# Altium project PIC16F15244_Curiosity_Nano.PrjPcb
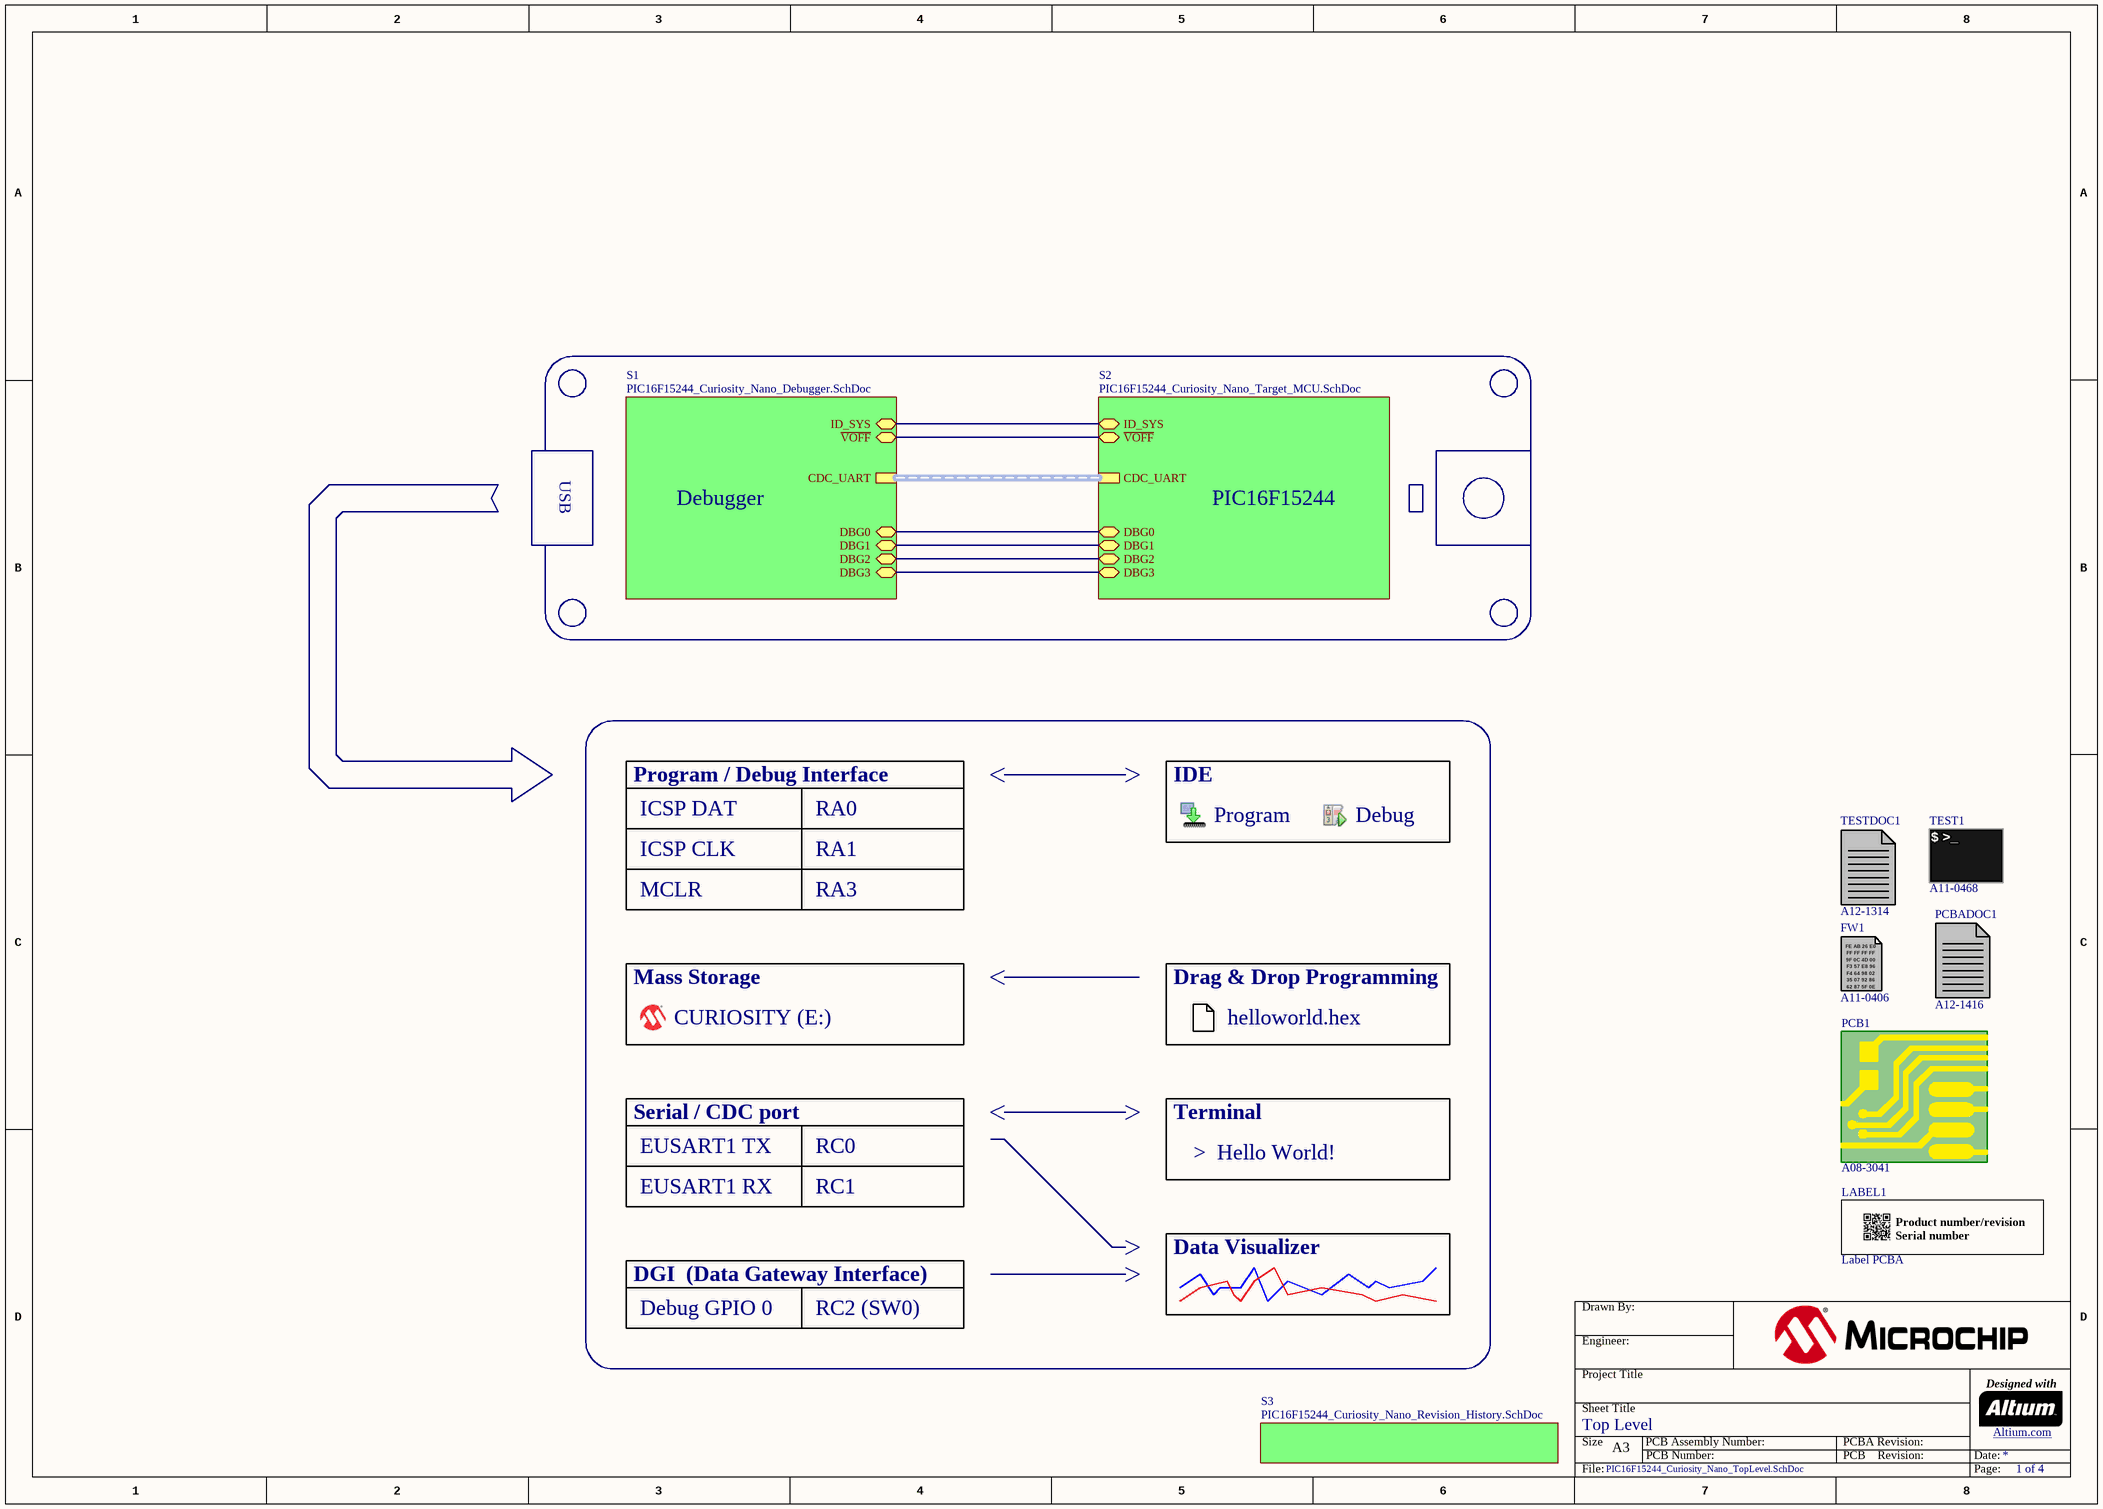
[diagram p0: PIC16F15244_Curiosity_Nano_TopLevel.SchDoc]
AN_PCB: A08-3041; AN_PCBA: A09-3317; PCB_rev: 1; PCBA_rev: 1; Project_Drawn_By: PB; Project_Engineer: PB; Target_Name: PIC16F15244
4 sheets, 64 parts. Net scope: hierarchical (ports join the sheet entries above them; power ports are global).
Board file: PIC16F15244_Curiosity_Nano.PcbDoc
Sheets:
  PIC16F15244_Curiosity_Nano_TopLevel.SchDoc
    S2 = PIC16F15244_Curiosity_Nano_Target_MCU.SchDoc
    S1 = PIC16F15244_Curiosity_Nano_Debugger.SchDoc
    S3 = PIC16F15244_Curiosity_Nano_Revision_History.SchDoc

## Sheet PIC16F15244_Curiosity_Nano_TopLevel.SchDoc: Top Level
size A3; Organization: Microchip Norway; Address1: Brøsetvegen 164; Address2: N-7069 TRONDHEIM; Address3: NORWAY; DocumentNumber: A09-3317; Revision: 1; SheetNumber: 1; SheetTotal: 4; DrawnBy: PB; Engineer: PB; PageSetup: Record=PageOptions¦CenterHorizontal=True¦CenterVertical=True¦PrintScale=1.01¦XCorrection=1.00¦YCorrection=1.00¦PrintKind=1¦BorderSize=5000000¦LeftOffset=0¦BottomOffset=0¦Orientation=2¦PaperLength=1000¦PaperWidth=1000¦Scale=100¦PaperSource=7¦PrintQuality=-4¦MediaType=1¦DitherType=10¦PaperKind=A3 (297 x 420 mm)¦PrintScaleMode=1; ProjectTitle: PIC16F15244 Curiosity Nano; PCBNumber: A08-3041; PCBRevision: 1

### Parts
FW1  AN: A11-0406  (mechanical)
LABEL1  value Label PCBA  [AP8-00317]
PCB1  AN: A08-3041  (mechanical)
PCBADOC1  AN: A12-1416  (mechanical)
TEST1  AN: A11-0468  (mechanical)
TESTDOC1  AN: A12-1314  (hidden comment: Use test fixture A13-0177)  (mechanical)

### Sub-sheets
S1 = PIC16F15244_Curiosity_Nano_Debugger.SchDoc: CDC_UART (harness UART), DBG2 (bidir), DBG1 (bidir), DBG3 (bidir), DBG0 (bidir), ~{VOFF} (bidir), ID_SYS (bidir)
S2 = PIC16F15244_Curiosity_Nano_Target_MCU.SchDoc: DBG0 (bidir), CDC_UART (harness UART), DBG1 (bidir), DBG3 (bidir), DBG2 (bidir), ~{VOFF} (bidir), ID_SYS (bidir)
S3 = PIC16F15244_Curiosity_Nano_Revision_History.SchDoc: no entries

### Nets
DBG0: sheet S2/DBG0, sheet S1/DBG0
DBG1: sheet S2/DBG1, sheet S1/DBG1
DBG2: sheet S2/DBG2, sheet S1/DBG2
DBG3: sheet S2/DBG3, sheet S1/DBG3
ID_SYS: sheet S2/ID_SYS, sheet S1/ID_SYS
~{VOFF}: sheet S2/~{VOFF}, sheet S1/~{VOFF}

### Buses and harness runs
harness sheet S1/CDC_UART = sheet S2/CDC_UART

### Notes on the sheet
- USB
- Debugger
- Program / Debug Interface
- IDE
- ICSP DAT
- ICSP CLK
- RA1
- RA0
- Program
- Debug
- MCLR
- RA3
- Mass Storage
- Drag & Drop Programming
- CURIOSITY (E:)
- helloworld.hex
- Serial / CDC port
- Terminal
- EUSART1 TX
- RC0
- >  Hello World!
- EUSART1 RX
- RC1
- Data Visualizer
- DGI  (Data Gateway Interface)
- Debug GPIO 0
- RC2 (SW0)

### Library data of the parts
FW1 = A11-0406: nEDBG firmware; PartGroup: Software,Firmware,Tools
LABEL1 = A09-0611: PCBA identification label PP Top White Gloss; Manufacturer: ACT Logimark AS; MPN: 505462; PartGroup: Mechanical devices,Packaging materials,Printed Labels,PCBA
PCB1 = A08-3041: PIC16F15244 Curiosity Nano PCB documentation; PartGroup: Mechanical devices,Printed circuit boards
PCBADOC1 = A12-1416: PIC16F15244 Curiosity Nano PCBA documentation; PartGroup: Documentation,PCBA Documents,Atmel; Value: A09-3317 PCBA files
TEST1 = A11-0468: Fixture test for PIC16F15244 Curiosity Nano; PartGroup: Software,Test software,Starter Kit; Value: PIC16F15244 Curiosity Nano test
TESTDOC1 = A12-1314: Generic Test Instructions for Curiosity Nano; PartGroup: Documentation,Procedures,Test Instructions; Value: Curiosity Nano Test Instructions

## Sheet PIC16F15244_Curiosity_Nano_Target_MCU.SchDoc: Target MCU
size A3; Organization: Microchip Norway; Address1: Brøsetvegen 164; Address2: N-7069 TRONDHEIM; Address3: NORWAY; DocumentNumber: A09-3317; Revision: 1; SheetNumber: 2; SheetTotal: 4; DrawnBy: PB; Engineer: PB; PageSetup: Record=PageOptions¦CenterHorizontal=True¦CenterVertical=True¦PrintScale=1.01¦XCorrection=1.00¦YCorrection=1.00¦PrintKind=1¦BorderSize=5000000¦LeftOffset=0¦BottomOffset=0¦Orientation=2¦PaperLength=1000¦PaperWidth=1000¦Scale=100¦PaperSource=7¦PrintQuality=-4¦MediaType=1¦DitherType=10¦PaperKind=A3 (297 x 420 mm)¦PrintScaleMode=1; ProjectTitle: PIC16F15244 Curiosity Nano; PCBNumber: A08-3041; PCBRevision: 1
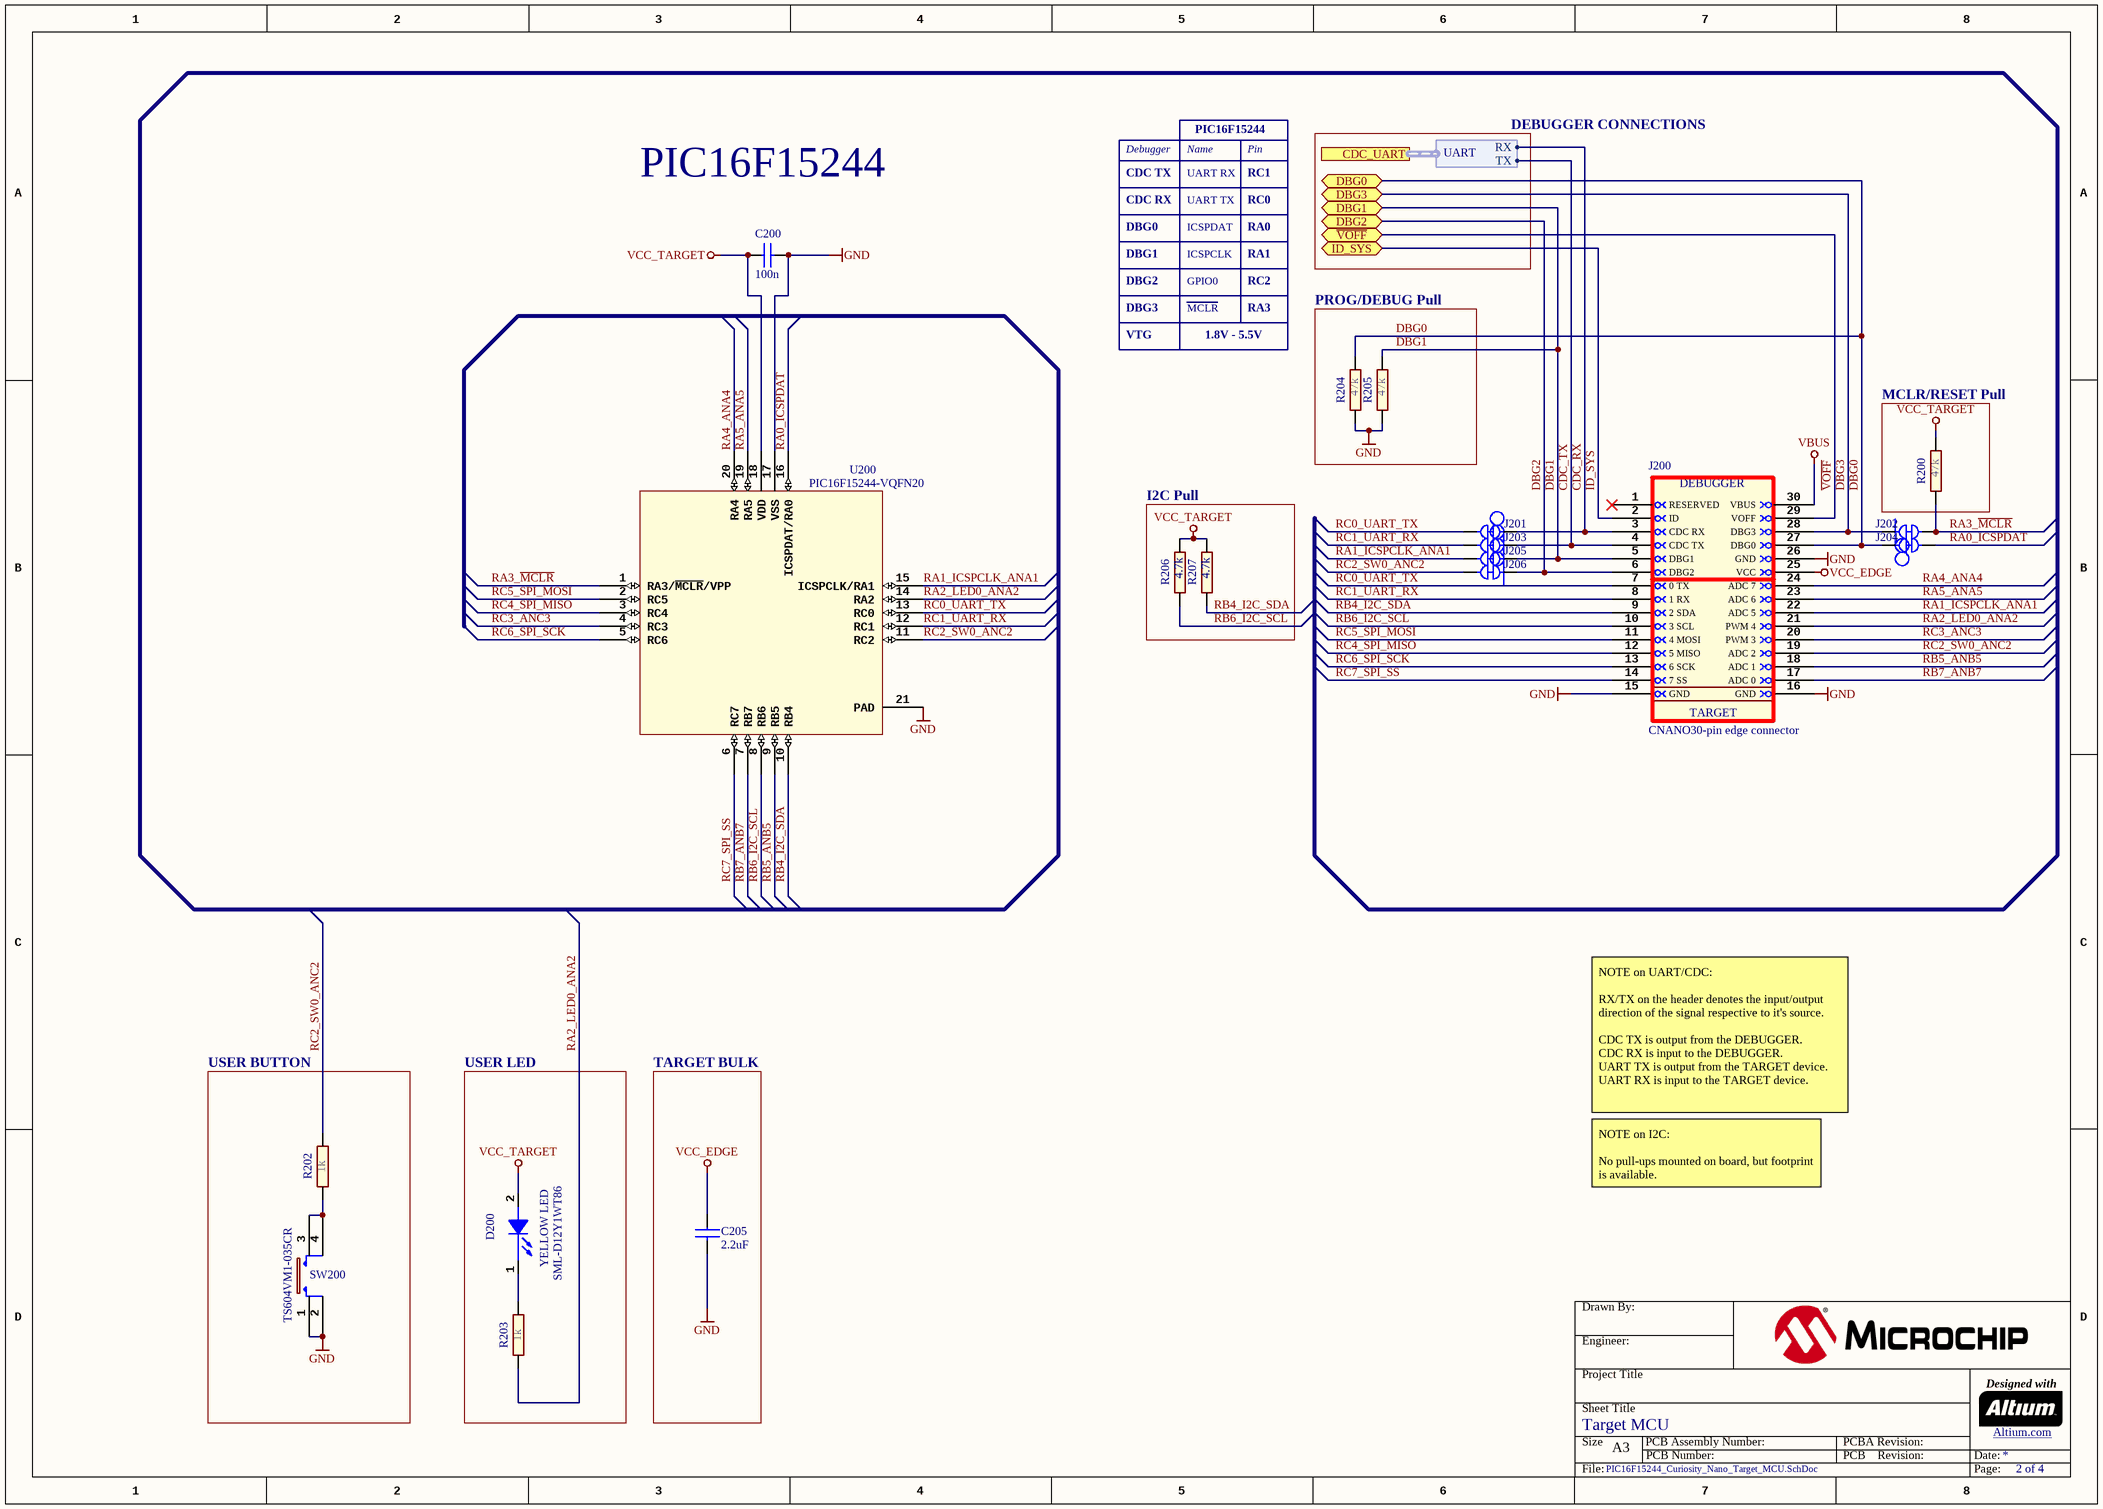
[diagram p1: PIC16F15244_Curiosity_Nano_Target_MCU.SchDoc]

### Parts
C200  value 100n  [AP1-00053]
C205  value 2.2uF  [AP1-00053]
D200  value YELLOW LED  MPN: SML-D12Y1WT86  [AP4-00169]
J200  value CNANO30-pin edge connector  [AP8-01110]  (no BOM)
J201  (no value)  [AP8-01166]  (net tie, no BOM)
J202  (no value)  [AP8-01166]  (net tie, no BOM)
J203  (no value)  [AP8-01166]  (net tie, no BOM)
J204  (no value)  [AP8-01166]  (net tie, no BOM)
J205  (no value)  [AP8-01166]  (net tie, no BOM)
J206  (no value)  [AP8-01166]  (net tie, no BOM)
R200  value 47k  [AP2-00011]
R202  value 1k  [AP2-00011]
R203  value 1k  [AP2-00011]
R204  value 47k  [AP2-00011]
R205  value 47k  [AP2-00011]
R206  value 4.7k  [AP2-00000]
R207  value 4.7k  [AP2-00000]
SW200  value TS604VM1-035CR  [AP8-00137]  (hidden comment: Rating: DC 12V 50mA / Max 0.1 ohm contact resistance)
U200  value PIC16F15244-VQFN20  [AP6-00494]

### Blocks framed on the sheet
PROG/DEBUG Pull: R204 R205
MCLR/RESET Pull: R200
I2C Pull: R206 R207
USER BUTTON: R202 SW200
USER LED: D200 R203
TARGET BULK: C205

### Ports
CDC_UART (harness UART), DBG0 (bidir), DBG1 (bidir), DBG2 (bidir), DBG3 (bidir), ID_SYS (bidir), ~{VOFF} (bidir)

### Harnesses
UART: TX, RX

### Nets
GND: C200.2 C205.2 J200.15(GND) J200.16(GND) J200.26(GND) R204.2 R205.2 SW200.1 SW200.2 U200.17(VSS) U200.21(PAD)
VBUS: J200.30(VBUS)
VCC_EDGE: C205.1 J200.25(VCC)
VCC_TARGET: C200.1 D200.2(ANODE) R200.1 R206.1 R207.1 U200.18(VDD)
CDC_RX: J200.3(CDC_RX) J201.1 ; port CDC_UART.RX
CDC_TX: J200.4(CDC_TX) J203.1 ; port CDC_UART.TX
DBG0: J200.27(DBG0) J204.1 R204.1 ; port DBG0
DBG1: J200.5(DBG1) J205.1 R205.1 ; port DBG1
DBG2: J200.6(DBG2) J206.1 ; port DBG2
DBG3: J200.28(DBG3) J202.1 ; port DBG3
ID_SYS: J200.2(ID) ; port ID_SYS
RA0_ICSPDAT: J204.2 U200.16(ICSPDAT/RA0)
RA1_ICSPCLK_ANA1: J200.22(ADC_5) J205.2 U200.15(ICSPCLK/RA1)
RA2_LED0_ANA2: J200.21(PWM_4) R203.1 U200.14(RA2)
RA3_~{MCLR}: J202.2 R200.2 U200.1(RA3/~{MCLR}/VPP)
RA4_ANA4: J200.24(ADC_7) U200.20(RA4)
RA5_ANA5: J200.23(ADC_6) U200.19(RA5)
RB4_I2C_SDA: J200.9(2_SDA) R207.2 U200.10(RB4)
RB5_ANB5: J200.18(ADC_1) U200.9(RB5)
RB6_I2C_SCL: J200.10(3_SCL) R206.2 U200.8(RB6)
RB7_ANB7: J200.17(ADC_0) U200.7(RB7)
RC0_UART_TX: J200.7(0_TX) J201.2 U200.13(RC0)
RC1_UART_RX: J200.8(1_RX) J203.2 U200.12(RC1)
RC2_SW0_ANC2: J200.19(ADC_2) J206.2 R202.1 U200.11(RC2)
RC3_ANC3: J200.20(PWM_3) U200.4(RC3)
RC4_SPI_MISO: J200.12(5_MISO) U200.3(RC4)
RC5_SPI_MOSI: J200.11(4_MOSI) U200.2(RC5)
RC6_SPI_SCK: J200.13(6_SCK) U200.5(RC6)
RC7_SPI_SS: J200.14(7_SS) U200.6(RC7)
~{VOFF}: J200.29(VOFF) ; port ~{VOFF}
NetD200_1: D200.1(CATHODE) R203.2
NetR202_2: R202.2 SW200.3 SW200.4

Not connected (* = marked no-connect by the designer): J200 1(RESERVED)*

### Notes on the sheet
- Debugger
- CDC TX
- UART RX
- Name
- RC1
- Pin
- DEBUGGER CONNECTIONS
- DBG0
- CDC RX
- ICSPDAT
- UART TX
- RA0
- RC0
- DBG1
- DBG2
- DBG3
- ICSPCLK
- GPIO0
- MCLR
- RA1
- RC2
- RA3
- VTG
- 1.8V - 5.5V
- NOTE on UART/CDC:
  RX/TX on the header denotes the input/output direction of the signal respective to it's source.
  CDC TX is output from the DEBUGGER.
  CDC RX is input to the DEBUGGER.
  UART TX is output from the TARGET device.
  UART RX is input to the TARGET device.
- NOTE on I2C:
  No pull-ups mounted on board, but footprint is available.

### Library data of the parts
C200 = A01-0246: Ceramic capacitor, SMD 0402, X7R, 16V, +/-10%; Manufacturer: Kemet; MPN: C0402C104K4RACTU; PartGroup: Capacitors,Ceramic,SMD 0402; TemperatureRange: -55 - +125 deg C
C205 = A01-0493: CAP CER 2.2UF 10V 10% X5R 0402; PartGroup: Capacitors,Ceramic,SMD 0402; Manufacturer: tdk; MPN: C1005X5R1A225K; Tolerance: +/-10%; TemperatureRange: -55 to 85C
D200 = A10-0218: LED, SMD 0603, Yellow, Wave length=590nm, 100mcd @ (20mA, 2.2Vf) rohm; PartGroup: Opto,LEDs,SMD; TemperatureRange: -40 to +85
J200 = A08-2846: Curiosity Nano 30-pin edge connector with castellations, 100-mil pitch.; PartGroup: Mechanical devices,Connectors,Pin headers
J201-J206 = A08-2981: Closed Link 0402 w/50mil hole; PartGroup: Mechanical devices,PCB implemented components
R200 R204 R205 = A02-0252: Thick film resistor, SMD 0402, 1/16W, 1%; Manufacturer: KOA; MPN: RK73H1ETTP4702F; PartGroup: Resistors,SMD,0402 1%; TemperatureRange: -55 - +125 deg C
R202 = A02-0212: Thick film resistor, SMD 0402, 1/16W, 1%; Manufacturer: ASJ Holdings; MPN: CR10-1001-FK; PartGroup: Resistors,SMD,0402 1%; TemperatureRange: -55 - +125 deg C
R203 = A02-0212: Thick film resistor, SMD 0402, 1/16W, 1%; PartGroup: Resistors,SMD,0402 1%; Manufacturer: ASJ Holdings; MPN: CR10-1001-FK; TemperatureRange: -55 - +125 deg C
R206 R207 = A02-1016: Thick film resistror, SMD 0402, 1/16W, 1%; PartGroup: Resistors,SMD,0402 1%; Manufacturer: Yageo; MPN: RC0402FR-074K7L; TemperatureRange: -55 to +155 deg C
SW200 = A08-2830: SWITCH, SMD, 260gf, 6.4mm X 6.2mm; PartGroup: Mechanical devices,Switches,SMD; Manufacturer: Dailywell Electronics Co.LTD; MPN: TS604VM1-035CR-R; TemperatureRange: -40 - +85 deg C
U200 = A06-1719: PIC 8-bit RISC MCU, VQFN-20, 3mm x 3mm; PartGroup: Integrated Circuits,MCU, MPU, DSP,PIC; Manufacturer: Microchip; MPN: PIC16F15244-I/REB; TemperatureRange: -40°C to 85°C

## Sheet PIC16F15244_Curiosity_Nano_Debugger.SchDoc: Debugger
size A3; Organization: Microchip Norway; Address1: Brøsetvegen 164; Address2: N-7069 TRONDHEIM; Address3: NORWAY; DocumentNumber: A09-3317; Revision: 1; SheetNumber: 3; SheetTotal: 4; DrawnBy: PB; Engineer: PB; PageSetup: Record=PageOptions¦CenterHorizontal=True¦CenterVertical=True¦PrintScale=1.01¦XCorrection=1.00¦YCorrection=1.00¦PrintKind=1¦BorderSize=5000000¦LeftOffset=0¦BottomOffset=0¦Orientation=2¦PaperLength=1000¦PaperWidth=1000¦Scale=100¦PaperSource=7¦PrintQuality=-4¦MediaType=1¦DitherType=10¦PaperKind=A3 (297 x 420 mm)¦PrintScaleMode=1; ProjectTitle: PIC16F15244 Curiosity Nano; PCBNumber: A08-3041; PCBRevision: 1
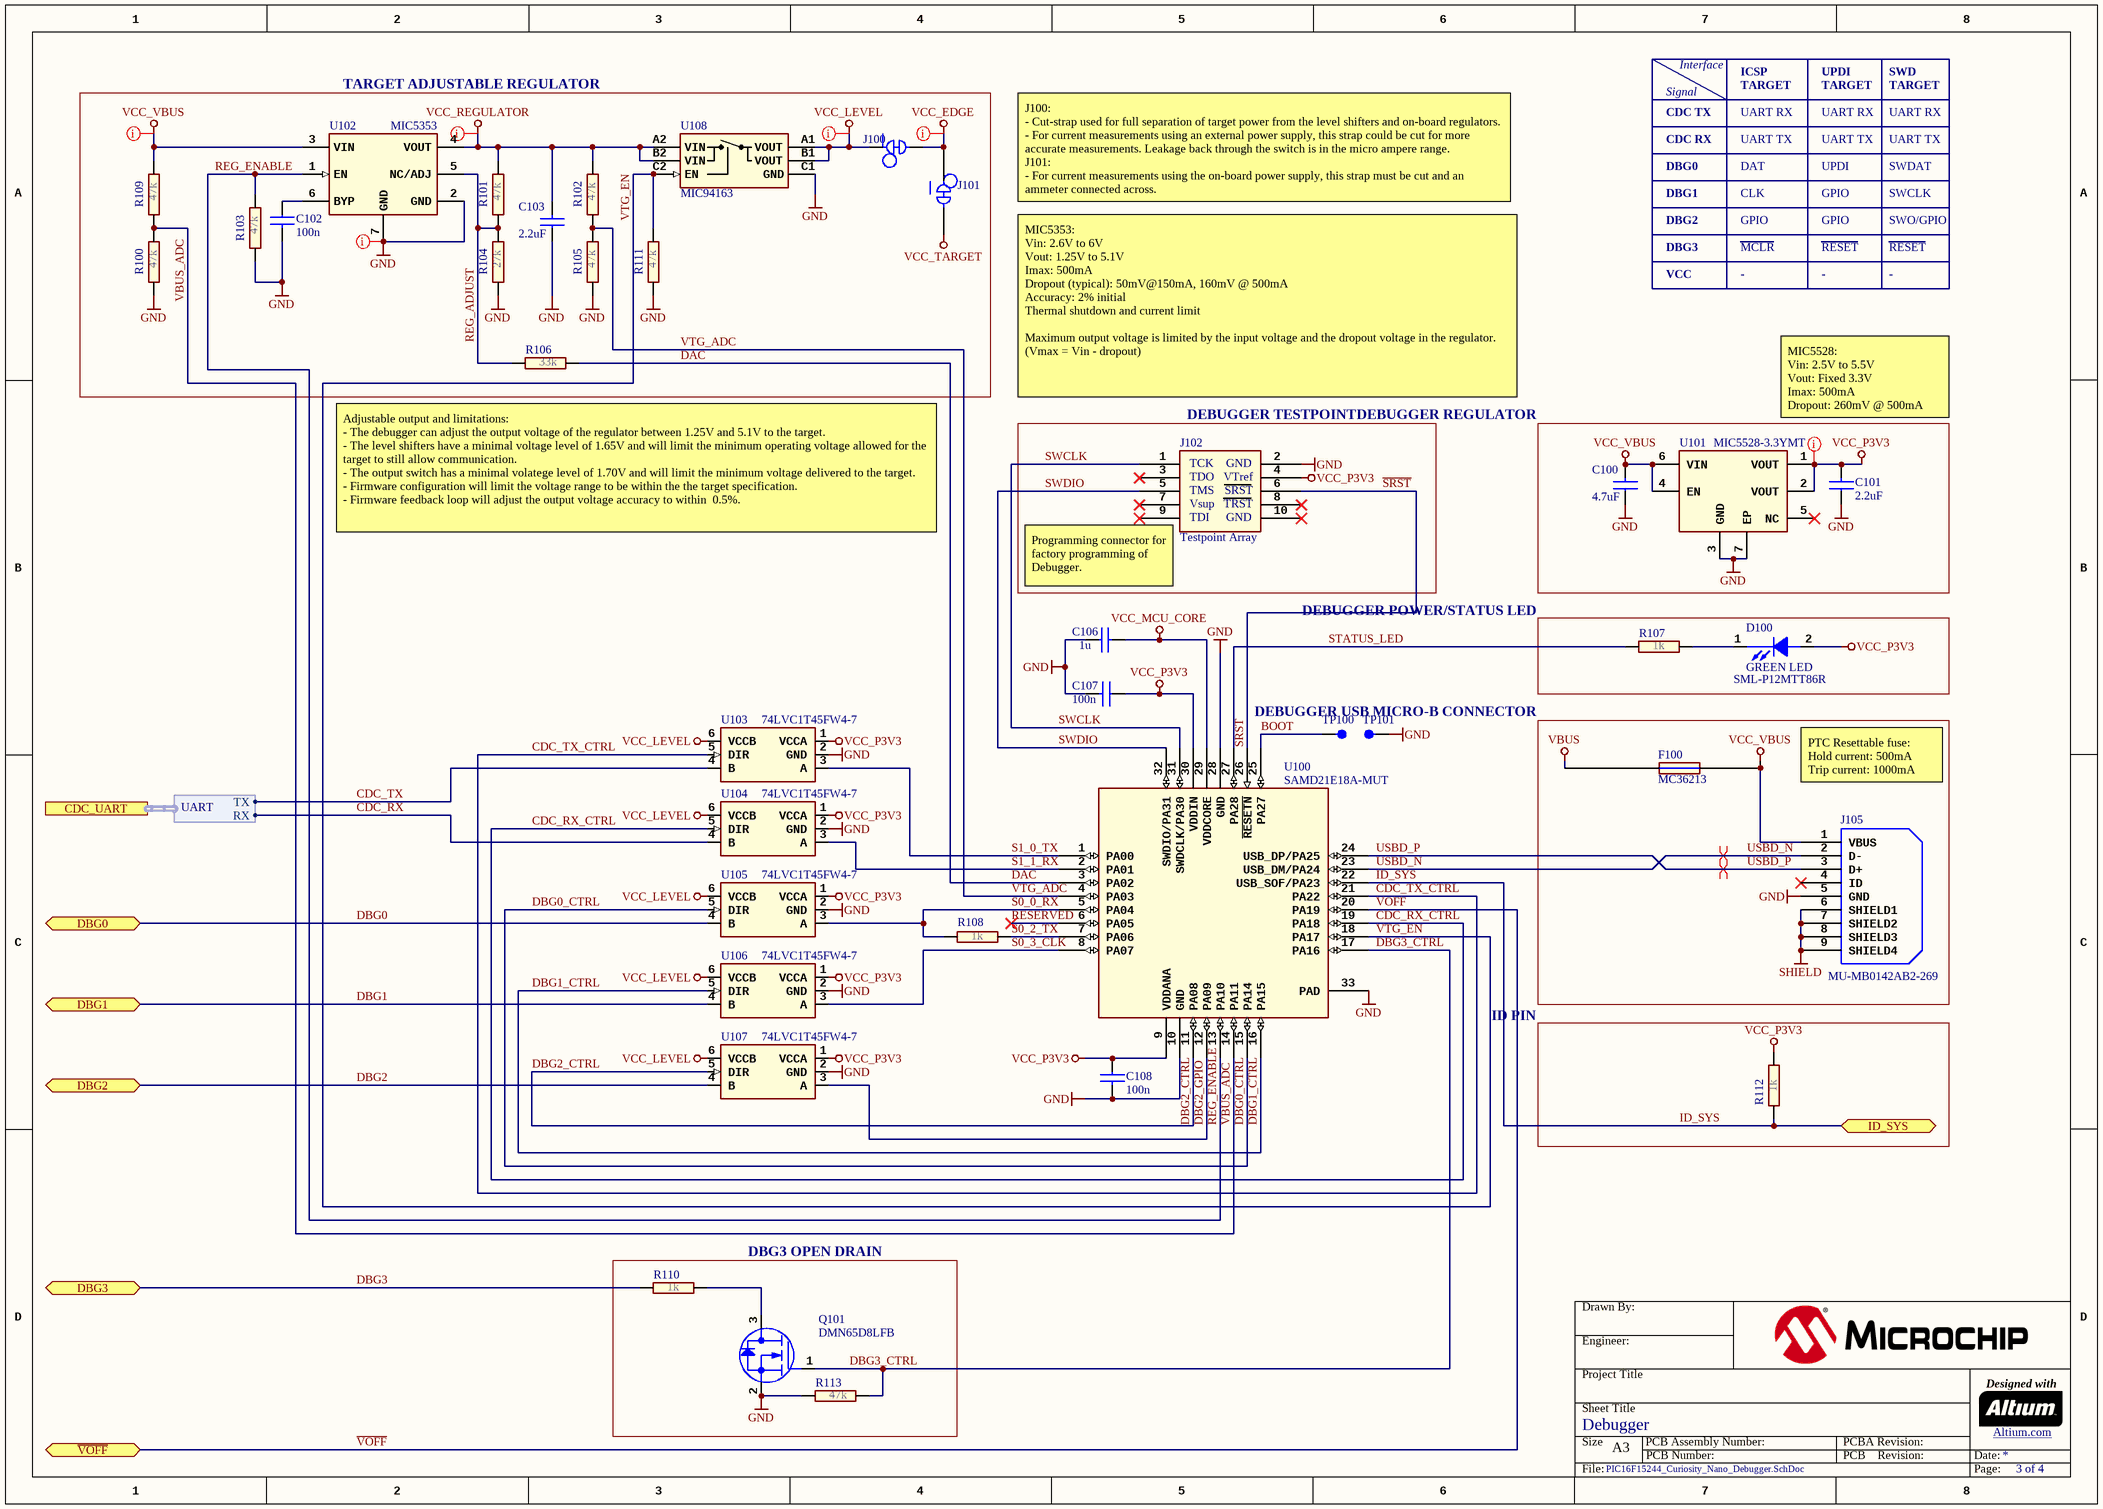
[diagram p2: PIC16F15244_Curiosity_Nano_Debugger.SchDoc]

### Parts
C100  value 4.7uF  [AP1-00039]
C101  value 2.2uF  [AP1-00053]  (hidden comment: Farnell no: 1288200)
C102  value 100n  [AP1-00053]
C103  value 2.2uF  [AP1-00053]
C106  value 1u  [AP1-00053]
C107  value 100n  [AP1-00053]
C108  value 100n  [AP1-00053]
D100  value GREEN LED  MPN: SML-P12MTT86R  [AP4-00160]  (hidden comment: Replacement to A10-0183 / Not proven to be as good at If = 1mA)
F100  value MC36213  [AP2-00002]  (hidden comment: Farnell no: 1861197)
J100  (no value)  [AP8-00595]  (net tie, no BOM)
J101  (no value)  [AP8-01183]  (net tie, no BOM)
J102  value Testpoint Array  [AP8-00997]  (no BOM)
J105  value MU-MB0142AB2-269  [AP8-01099]
Q101  value DMN65D8LFB  [AP5-00056]
R100  value 47k  [AP2-00011]
R101  value 47k  [AP2-00011]
R102  value 47k  [AP2-00011]
R103  value 47k  [AP2-00011]
R104  value 27k  [AP2-00011]
R105  value 47k  [AP2-00011]
R106  value 33k  [AP2-00011]
R107  value 1k  [AP2-00011]
R108  value 1k  [AP2-00011]
R109  value 47k  [AP2-00011]
R110  value 1k  [AP2-00011]
R111  value 47k  [AP2-00011]
R112  value 1k  [AP2-00011]
R113  value 47k  [AP2-00011]
TP100  PCB implemented component.  [AP8-00870]  (value not drawn)  (no BOM)
TP101  PCB implemented component.  [AP8-00870]  (value not drawn)  (no BOM)
U100  value SAMD21E18A-MUT  [AP6-00418]  (hidden comment: QFN32)
U101  value MIC5528-3.3YMT  [AP6-00481]
U102  value MIC5353  [AP6-00504]  (hidden comment: Marking code: AAR)
U103  value 74LVC1T45FW4-7  [AP6-00505]  (hidden comment: 1.05 x 1.05 x 0.4mm)
U104  value 74LVC1T45FW4-7  [AP6-00505]  (hidden comment: 1.05 x 1.05 x 0.4mm)
U105  value 74LVC1T45FW4-7  [AP6-00505]  (hidden comment: 1.05 x 1.05 x 0.4mm)
U106  value 74LVC1T45FW4-7  [AP6-00505]  (hidden comment: 1.05 x 1.05 x 0.4mm)
U107  value 74LVC1T45FW4-7  [AP6-00505]  (hidden comment: 1.05 x 1.05 x 0.4mm)
U108  value MIC94163  [AP6-00513]

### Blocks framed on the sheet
TARGET ADJUSTABLE REGULATOR: C102 C103 J100 J101 R100-R106 R109 R111 U102 U108
DEBUGGER TESTPOINT: J102
DEBUGGER REGULATOR: C100 C101 U101
DEBUGGER POWER/STATUS LED: D100 R107
DEBUGGER USB MICRO-B CONNECTOR: F100 J105
ID PIN: R112
DBG3 OPEN DRAIN: Q101 R110 R113

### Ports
CDC_UART (harness UART), DBG0 (bidir), DBG1 (bidir), DBG2 (bidir), DBG3 (bidir), ID_SYS (bidir), ~{VOFF} (bidir)

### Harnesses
UART: RX, TX

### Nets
GND: C100.1 C101.1 C102.2 C103.1 C106.1 C107.2 C108.2 J102.2 J105.5(GND) Q101.2(S) R100.2 R103.2 R104.1 R105.1 R111.2 R113.2 TP101.1 U100.10(GND) U100.28(GND) U100.33(PAD) U101.3(GND) U101.7(EP) U102.2(GND) U102.7(GND) U103.2(GND) U104.2(GND) U105.2(GND) U106.2(GND) U107.2(GND) U108.C1(GND)
SHIELD: J105.6(SHIELD1) J105.7(SHIELD2) J105.8(SHIELD3) J105.9(SHIELD4)
VBUS: F100.1
VCC_EDGE: J100.2 J101.1
VCC_LEVEL: J100.1 U103.6(VCCB) U104.6(VCCB) U105.6(VCCB) U106.6(VCCB) U107.6(VCCB) U108.A1(VOUT) U108.B1(VOUT)
VCC_MCU_CORE: C106.2 U100.29(VDDCORE)
VCC_P3V3: C101.2 C107.1 C108.1 D100.2(ANODE) J102.4 R112.1 U100.9(VDDANA) U100.30(VDDIN) U101.1(VOUT) U101.2(VOUT) U103.1(VCCA) U104.1(VCCA) U105.1(VCCA) U106.1(VCCA) U107.1(VCCA)
VCC_REGULATOR: C103.2 R101.1 R102.2 U102.4(VOUT) U108.A2(VIN) U108.B2(VIN)
VCC_TARGET: J101.2
VCC_VBUS: C100.2 F100.2 J105.1(VBUS) R109.2 U101.4(EN) U101.6(VIN) U102.3(VIN)
BOOT: TP100.1 U100.25(PA27)
CDC_RX: U104.4(B) ; port CDC_UART.RX
CDC_RX_CTRL: U100.19(PA18) U104.5(DIR)
CDC_TX: U103.4(B) ; port CDC_UART.TX
CDC_TX_CTRL: U100.21(PA22) U103.5(DIR)
DAC: R106.2 U100.3(PA02)
DBG0: U105.4(B) ; port DBG0
DBG0_CTRL: U100.15(PA14) U105.5(DIR)
DBG1: U106.4(B) ; port DBG1
DBG1_CTRL: U100.16(PA15) U106.5(DIR)
DBG2: U107.4(B) ; port DBG2
DBG2_CTRL: U100.11(PA08) U107.5(DIR)
DBG2_GPIO: U100.12(PA09) U107.3(A)
DBG3: R110.2 ; port DBG3
DBG3_CTRL: Q101.1(G) R113.1 U100.17(PA16)
ID_SYS: R112.2 U100.22(USB_SOF/PA23) ; port ID_SYS
REG_ADJUST: R101.2 R104.2 R106.1 U102.5(NC/ADJ)
REG_ENABLE: R103.1 U100.13(PA10) U102.1(EN)
RESERVED: U100.6(PA05)
S0_0_RX: R108.1 U100.5(PA04) U105.3(A)
S0_2_TX: R108.2 U100.7(PA06)
S0_3_CLK: U100.8(PA07) U106.3(A)
S1_0_TX: U100.1(PA00) U103.3(A)
S1_1_RX: U100.2(PA01) U104.3(A)
~{SRST}: J102.6 U100.26(~{RESETN})
STATUS_LED: R107.2 U100.27(PA28)
SWCLK: J102.1 U100.31(SWDCLK/PA30)
SWDIO: J102.5 U100.32(SWDIO/PA31)
USBD_N: J105.2(D-) U100.23(USB_DM/PA24)
USBD_P: J105.3(D+) U100.24(USB_DP/PA25)
~{VOFF}: U100.20(PA19) ; port ~{VOFF}
VBUS_ADC: R100.1 R109.1 U100.14(PA11)
VTG_ADC: R102.1 R105.2 U100.4(PA03)
VTG_EN: R111.1 U100.18(PA17) U108.C2(EN)
NetC102_1: C102.1 U102.6(BYP)
NetD100_1: D100.1(CATHODE) R107.1
NetQ101_3: Q101.3(D) R110.1

Not connected (* = marked no-connect by the designer): J102 3* 7* 8* 9* 10*; J105 4(ID)*; U101 5(NC)*

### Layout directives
net class Power: GND, VCC_EDGE, VCC_LEVEL, VCC_P3V3, VCC_REGULATOR, VCC_VBUS
differential pair: USBD_N, USBD_P

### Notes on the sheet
- Signal
- Interface
- ICSP
- TARGET
- UPDI
- SWD
- DBG0
- CDC TX
- CDC RX
- DAT
- UART RX
- UART TX
- SWDAT
- J100:
  - Cut-strap used for full separation of target power from the level shifters and on-board regulators.
  - For current measurements using an external power supply, this strap could be cut for more accurate measurements. Leakage back through the switch is in the micro ampere range.
  J101:
  - For current measurements using the on-board power supply, this strap must be cut and an ammeter connected across.
- DBG1
- DBG2
- CLK
- GPIO
- SWCLK
- SWO/GPIO
- DBG3
- VCC
- MCLR
- -
- RESET
- MIC5353:
  Vin: 2.6V to 6V
  Vout: 1.25V to 5.1V
  Imax: 500mA
  Dropout (typical): 50mV@150mA, 160mV @ 500mA
  Accuracy: 2% initial
  Thermal shutdown and current limit
  Maximum output voltage is limited by the input voltage and the dropout voltage in the regulator.
  (Vmax = Vin - dropout)
- MIC5528:
  Vin: 2.5V to 5.5V
  Vout: Fixed 3.3V
  Imax: 500mA
  Dropout: 260mV @ 500mA
- (near R106) Adjustable output and limitations:
  - The debugger can adjust the output voltage of the regulator between 1.25V and 5.1V to the target.
  - The level shifters have a minimal voltage level of 1.65V and will limit the minimum operating voltage allowed for the target to still allow communication.
  - The output switch has a minimal volatege level of 1.70V and will limit the minimum voltage delivered to the target.
  - Firmware configuration will limit the voltage range to be within the the target specification.
  - Firmware feedback loop will adjust the output voltage accuracy to within  0.5%.
- (near J102) Programming connector for factory programming of Debugger.
- PTC Resettable fuse:
  Hold current: 500mA
  Trip current: 1000mA

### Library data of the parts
C100 = A01-0377: Ceramic capacitor, SMD 0603, X5R, 10V, 10% (de31036); PartGroup: Capacitors,Ceramic,SMD 0603; Manufacturer: WALSIN Technology Corporation; MPN: 0603X475K100CT; TemperatureRange: -55 - +85 deg C
C101 = A01-0300: Ceramic capacitor, SMD 0402, X5R, 6.3V, +/-20%; PartGroup: Capacitors,Ceramic,SMD 0402; Manufacturer: Kemet; MPN: C0402C225M9PAC; Tolerance: Â±20%; TemperatureRange: -55Â°C to +85Â°C
C102 C107 C108 = A01-0246: Ceramic capacitor, SMD 0402, X7R, 16V, +/-10%; PartGroup: Capacitors,Ceramic,SMD 0402; Manufacturer: Kemet; MPN: C0402C104K4RACTU; TemperatureRange: -55 - +125 deg C
C103 = A01-0493: as C205 on sheet PIC16F15244_Curiosity_Nano_Target_MCU
C106 = A01-0286: Ceramic capacitor, SMD 0402, X5R, 6.3V, +/-10% (de26942); PartGroup: Capacitors,Ceramic,SMD 0402; Manufacturer: Kemet; MPN: C0402C105K9PAC; TemperatureRange: -55 to 85 deg C
D100 = A10-0213: LED, SMD 0402, Green, Wave length=569nm, 2.1mcd @ (1mA, 1.9Vf)rohm; PartGroup: Opto,LEDs,SMD; TemperatureRange: -40 to +85
F100 = A02-0622: Resetable PTC fuse, Ih = 0.5A, It = 1.0A, 0805 package; PartGroup: Resistors,Resettable fuses,SMD; Manufacturer: Multicomp; TemperatureRange: -40°C to + 85°C
J100 = A08-1454: Closed Link 0402; PartGroup: Mechanical devices,PCB implemented components
J101 = A08-3029: Closed Link with w/hole for 1x2 100mil header; PartGroup: Mechanical devices,PCB implemented components; Value: Closed Link 1x2 100mil header
J102 = A08-2568: 10-pin Testpoint Array, 0.8mm Pad, 1.27mm Pitch; PartGroup: Mechanical devices,PCB implemented components,PCB plane connectors
J105 = A08-2839: USB micro AB, Surface mount signals and DIP shield; PartGroup: Mechanical devices,Connectors,USB; Manufacturer: Allen Creations Corp.; TemperatureRange: -30Â°C to +80Â°C
Q101 = A05-0180: N-channel MOSFET, DFN1006-3 (SOT883), 60V, 330mA, 4Ohm; PartGroup: Transistors,Small signal FET,SMD; Manufacturer: Diodes Incorporated; MPN: DMN65D8LFB-7; TemperatureRange: -55Â°C to +150Â°C
R100-R102 R105 R109 R111 R113 = A02-0252: as R200 on sheet PIC16F15244_Curiosity_Nano_Target_MCU
R103 = A02-0252: Thick film resistor, SMD 0402, 1/16W, 1%; PartGroup: Resistors,SMD,0402 1%; Manufacturer: KOA; MPN: RK73H1ETTP4702F; TemperatureRange: -55 - +125 deg C
R104 = A02-0246: Thick film resistor, SMD 0402, 1/16W, 1%; Manufacturer: Yageo; MPN: RC0402FR-0727KL; PartGroup: Resistors,SMD,0402 1%; TemperatureRange: -55 - +125 deg C
R106 = A02-0248: Thick film resistor, SMD 0402, 1/16W, 1%; Manufacturer: ASJ Holdings; MPN: CR10-3302-FK; PartGroup: Resistors,SMD,0402 1%; TemperatureRange: -55 - +125 deg C
R107 R108 R110 R112 = A02-0212: as R203 on sheet PIC16F15244_Curiosity_Nano_Target_MCU
TP100 TP101 = A08-2176: SMD Test point - 0.8mm; PartGroup: Mechanical devices,Connectors,Test points
U100 = A06-1205: 32-bit RISC MCU 32pin; PartGroup: Integrated Circuits,MCU, MPU, DSP,ARM MCU; Manufacturer: Microchip; MPN: ATSAMD21E18A-MUT; TemperatureRange: -40Â°C to +85Â°C
U101 = A06-1475: LDO 3.3V 0.5A 6TDFN; PartGroup: Integrated Circuits,Regulators,Linear; Manufacturer: Microchip; MPN: MIC5528-3.3YMT-T5; TemperatureRange: -40Â°C ~ 125Â°C
U102 = A06-1578: 500mA Ultra Low Dropout LDO regulator, 2% accuracy, 1.6x1.6mm MLF; PartGroup: Integrated Circuits,Regulators,Linear; Manufacturer: Microchip; MPN: MIC5353YMT-TR; TemperatureRange: -40Â°C to +125Â°C
U103-U107 = A06-1580: Single-Bit Dual-Supply Transceive, 1.65-5.5 Translation and 3-State Outputs; PartGroup: Integrated Circuits,Interface ICs,Level translators; Manufacturer: Diodes Incorporated; TemperatureRange: -40C - 125C
U108 = A06-1613: Loadswitch, Rds(on) = 14.5mohm, 1.0mm x 1.5mm WLCSP, reverse blocking; PartGroup: Integrated Circuits,General linear,Analog switch, bus switch and MUX; Manufacturer: Microchip; MPN: MIC94163YCS-TR; TemperatureRange: -40Â°C to +125Â°C

## Sheet PIC16F15244_Curiosity_Nano_Revision_History.SchDoc: Revision History
size A3; Organization: Microchip Norway; Address1: Brøsetvegen 164; Address2: N-7069 TRONDHEIM; Address3: NORWAY; DocumentNumber: A09-3317; Revision: 1; SheetNumber: 4; SheetTotal: 4; DrawnBy: PB; Engineer: PB; PageSetup: Record=PageOptions¦CenterHorizontal=True¦CenterVertical=True¦PrintScale=1.01¦XCorrection=1.00¦YCorrection=1.00¦PrintKind=1¦BorderSize=5000000¦LeftOffset=0¦BottomOffset=0¦Orientation=2¦PaperLength=1000¦PaperWidth=1000¦Scale=100¦PaperSource=7¦PrintQuality=-4¦MediaType=1¦DitherType=10¦PaperKind=A3 (297 x 420 mm)¦PrintScaleMode=1; ProjectTitle: PIC16F15244 Curiosity Nano; PCBNumber: A08-3041; PCBRevision: 1
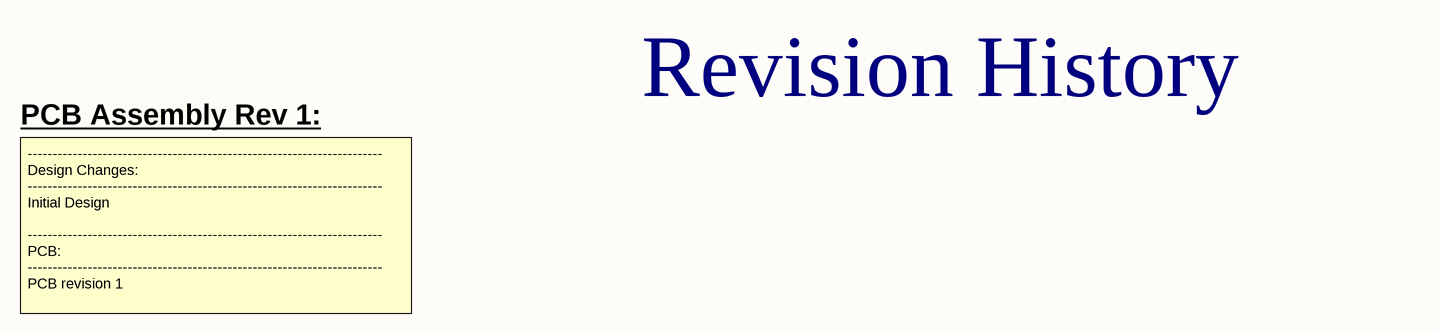
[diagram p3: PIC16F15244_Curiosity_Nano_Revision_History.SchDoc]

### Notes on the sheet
- PCB Assembly Rev 1:
- Revision History
- -----------------------------------------------------------------------
  Design Changes:
  -----------------------------------------------------------------------
  Initial Design
  -----------------------------------------------------------------------
  PCB:
  -----------------------------------------------------------------------
  PCB revision 1

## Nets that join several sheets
GND: PIC16F15244_Curiosity_Nano_Target_MCU (11 pins), PIC16F15244_Curiosity_Nano_Debugger (30 pins)
VBUS: PIC16F15244_Curiosity_Nano_Target_MCU (J200.30), PIC16F15244_Curiosity_Nano_Debugger (F100.1)
VCC_EDGE: PIC16F15244_Curiosity_Nano_Target_MCU (C205.1 J200.25), PIC16F15244_Curiosity_Nano_Debugger (J100.2 J101.1)
VCC_TARGET: PIC16F15244_Curiosity_Nano_Target_MCU (6 pins), PIC16F15244_Curiosity_Nano_Debugger (J101.2)
CDC_RX: PIC16F15244_Curiosity_Nano_Target_MCU (J200.3 J201.1), PIC16F15244_Curiosity_Nano_Debugger (U104.4)
CDC_TX: PIC16F15244_Curiosity_Nano_Target_MCU (J200.4 J203.1), PIC16F15244_Curiosity_Nano_Debugger (U103.4)
DBG0: PIC16F15244_Curiosity_Nano_Target_MCU (J200.27 J204.1 R204.1), PIC16F15244_Curiosity_Nano_Debugger (U105.4)
DBG1: PIC16F15244_Curiosity_Nano_Target_MCU (J200.5 J205.1 R205.1), PIC16F15244_Curiosity_Nano_Debugger (U106.4)
DBG2: PIC16F15244_Curiosity_Nano_Target_MCU (J200.6 J206.1), PIC16F15244_Curiosity_Nano_Debugger (U107.4)
DBG3: PIC16F15244_Curiosity_Nano_Target_MCU (J200.28 J202.1), PIC16F15244_Curiosity_Nano_Debugger (R110.2)
ID_SYS: PIC16F15244_Curiosity_Nano_Target_MCU (J200.2), PIC16F15244_Curiosity_Nano_Debugger (R112.2 U100.22)
~{VOFF}: PIC16F15244_Curiosity_Nano_Target_MCU (J200.29), PIC16F15244_Curiosity_Nano_Debugger (U100.20)

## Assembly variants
Default Assembly: not fitted R206 R207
